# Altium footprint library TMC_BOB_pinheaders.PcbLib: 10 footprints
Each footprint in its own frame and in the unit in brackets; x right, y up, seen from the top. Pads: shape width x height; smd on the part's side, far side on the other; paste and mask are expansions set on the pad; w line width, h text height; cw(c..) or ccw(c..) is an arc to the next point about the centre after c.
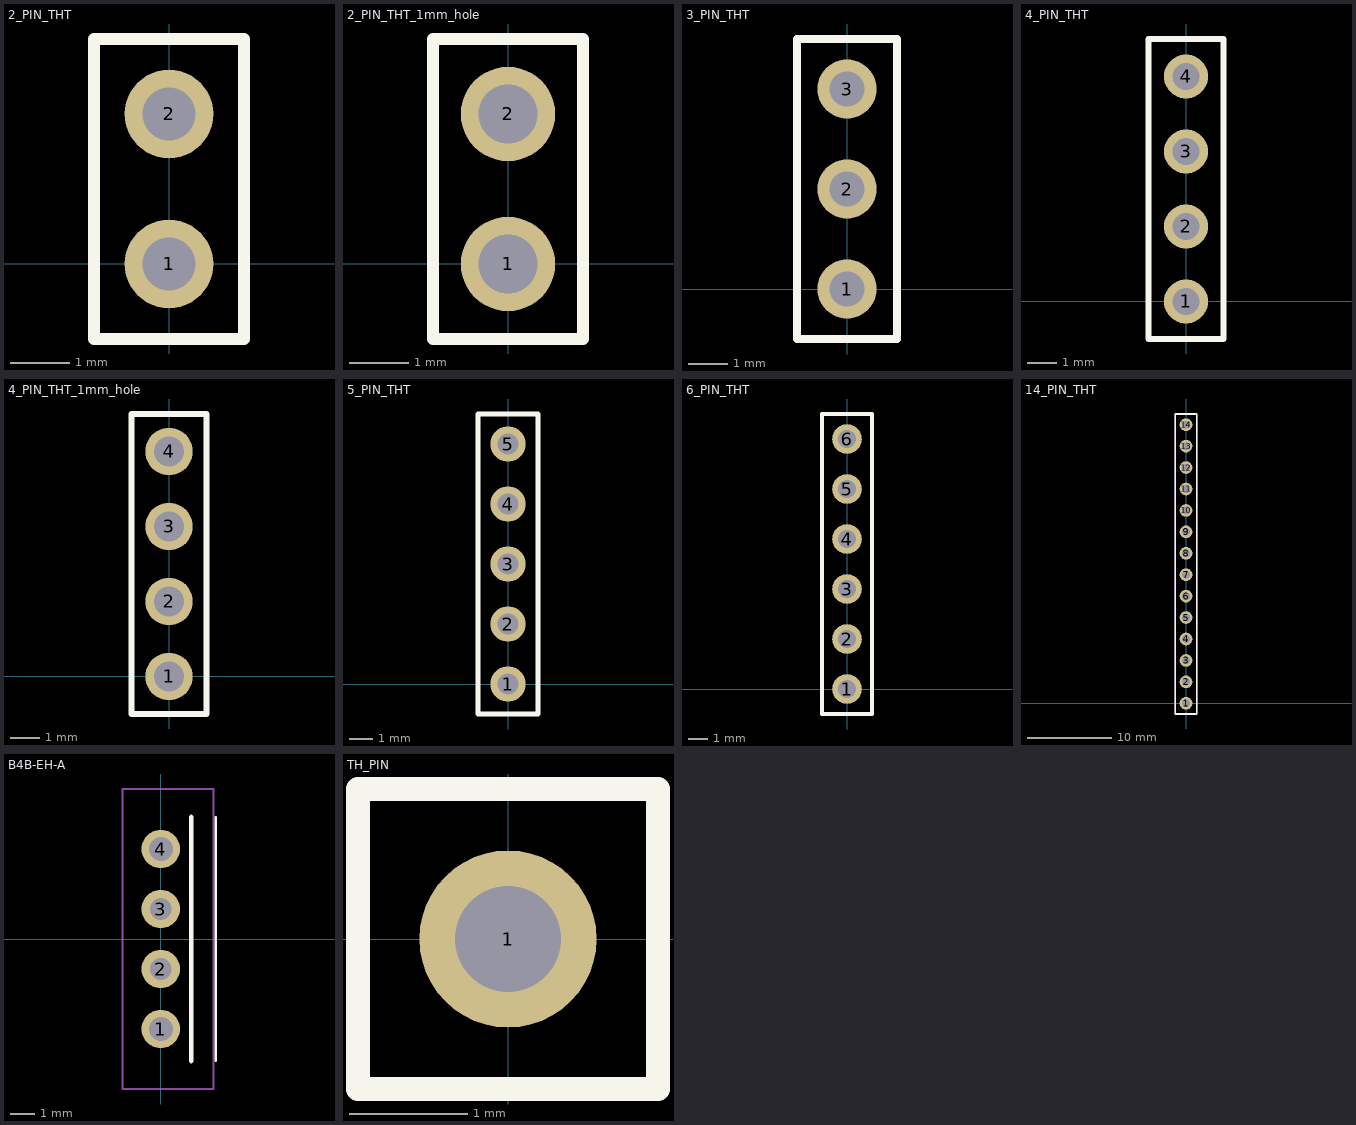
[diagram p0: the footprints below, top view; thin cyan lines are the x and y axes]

## 2_PIN_THT [mm]
pads (2):
  round 1.5 hole 0.9: 1(0,0) 2(0,2.54)
Top Overlay:
  lines w0.2: -1.27,-1.27 -1.27,3.81 1.27,3.81 1.27,-1.27 -1.27,-1.27
Bottom Overlay:
  lines w0.2: -1.27,-1.27 -1.27,3.81 1.27,3.81 1.27,-1.27 -1.27,-1.27
TopAsm:
  lines w0.051: -1.27,-1.27 -1.27,3.81 1.27,3.81 1.27,-1.27 -1.27,-1.27

## 2_PIN_THT_1mm_hole [mm]
pads (2):
  round 1.6 hole 1: 1(0,0) 2(0,2.54)
Top Overlay:
  lines w0.2: -1.27,-1.27 1.27,-1.27 1.27,3.81 -1.27,3.81 -1.27,-1.27
Bottom Overlay:
  lines w0.2: -1.27,-1.27 1.27,-1.27 1.27,3.81 -1.27,3.81 -1.27,-1.27
TopAsm:
  lines w0.051: -1.27,-1.27 1.27,-1.27 1.27,3.81 -1.27,3.81 -1.27,-1.27

## 3_PIN_THT [mm]
pads (3):
  round 1.5 hole 0.9: 1(0,0) 2(0,2.54) 3(0,5.08)
Top Overlay:
  lines w0.2: -1.27,-1.27 -1.27,6.35 1.27,6.35 1.27,-1.27 -1.27,-1.27
Bottom Overlay:
  lines w0.2: -1.27,-1.27 -1.27,6.35 1.27,6.35 1.27,-1.27 -1.27,-1.27
TopAsm:
  lines w0.051: -1.27,-1.27 1.27,-1.27 1.27,6.35 -1.27,6.35 -1.27,-1.27

## 4_PIN_THT [mm]
pads (4):
  round 1.5 hole 0.9: 1(0,0) 2(0,2.54) 3(0,5.08) 4(0,7.62)
Top Overlay:
  lines w0.2: -1.27,-1.27 -1.27,8.89 1.27,8.89 1.27,-1.27 -1.27,-1.27
Bottom Overlay:
  lines w0.2: -1.27,-1.27 1.27,-1.27 1.27,8.89 -1.27,8.89 -1.27,-1.27
TopAsm:
  lines w0.051: -1.27,-1.27 1.27,-1.27 1.27,8.89 -1.27,8.89 -1.27,-1.27

## 4_PIN_THT_1mm_hole [mm]
pads (4):
  round 1.6 hole 1: 1(0,0) 2(0,2.54) 3(0,5.08) 4(0,7.62)
Top Overlay:
  lines w0.2: -1.27,-1.27 -1.27,8.89 1.27,8.89 1.27,-1.27 -1.27,-1.27
Bottom Overlay:
  lines w0.2: -1.27,-1.27 1.27,-1.27 1.27,8.89 -1.27,8.89 -1.27,-1.27
TopAsm:
  lines w0.051: -1.27,-1.27 1.27,-1.27 1.27,8.89 -1.27,8.89 -1.27,-1.27

## 5_PIN_THT [mm]
pads (5):
  round 1.5 hole 0.9: 1(0,0) 2(0,2.54) 3(0,5.08) 4(0,7.62) 5(0,10.16)
Top Overlay:
  lines w0.2: -1.27,-1.27 1.27,-1.27 1.27,11.43 -1.27,11.43 -1.27,-1.27
Bottom Overlay:
  lines w0.2: -1.27,-1.27 1.27,-1.27 1.27,11.43 -1.27,11.43 -1.27,-1.27
TopAsm:
  lines w0.051: -1.27,-1.27 1.27,-1.27 1.27,11.43 -1.27,11.43 -1.27,-1.27

## 6_PIN_THT [mm]
pads (6):
  round 1.5 hole 0.9: 1(0,0) 2(0,2.54) 3(0,5.08) 4(0,7.62) 5(0,10.16) 6(0,12.7)
Top Overlay:
  lines w0.2: -1.27,-1.27 -1.27,13.97 1.27,13.97 1.27,-1.27 -1.27,-1.27
Bottom Overlay:
  lines w0.2: -1.27,-1.27 -1.27,13.97 1.27,13.97 1.27,-1.27 -1.27,-1.27
TopAsm:
  lines w0.051: -1.27,-1.27 1.27,-1.27 1.27,13.97 -1.27,13.97 -1.27,-1.27

## 14_PIN_THT [mm]
pads (14):
  round 1.5 hole 0.9: 1(0,0) 2(0,2.54) 3(0,5.08) 4(0,7.62) 5(0,10.16) 6(0,12.7) 7(0,15.24) 8(0,17.78) 9(0,20.32) 10(0,22.86) 11(0,25.4) 12(0,27.94) 13(0,30.48) 14(0,33.02)
Top Overlay:
  lines w0.2: -1.27,-1.27 1.27,-1.27 1.27,34.29 -1.27,34.29 -1.27,-1.27
Bottom Overlay:
  lines w0.2: -1.27,-1.27 -1.27,34.29 1.27,34.29 1.27,-1.27 -1.27,-1.27
TopAsm:
  lines w0.2: -1.27,-1.27 1.27,-1.27 1.27,13.97 1.27,29.21 1.27,34.29 -1.27,34.29 -1.27,29.21 -1.27,13.97 -1.27,-1.27

## B4B-EH-A [mm]
pads (4):
  round 1.6 hole 1: 1(0,-3.75) 4(0,3.75)
  round 1.6 hole 0.9: 2(0,-1.25) 3(0,1.25)
Top Overlay:
  lines w0.1: 2.286,-5.08 2.286,5.08
  lines w0.2: 1.27,-5.08 1.27,5.08
Bottom Overlay:
  lines w0.2: 1.27,-5.08 1.27,5.08
TopAsm:
  lines w0.051: 1.27,-5.08 1.27,5.08
  lines w0.075: -1.6,-6.25 2.2,-6.25 2.2,6.25 -1.6,6.25 -1.6,-6.25
3D body "B4B-EH-A.STEP": height 6, standoff -3.2, extent -1.6,-6.25 2.2,6.25

## TH_PIN [mm]
pads (1):
  round 1.5 hole 0.9: 1(0,0)
Top Overlay:
  lines w0.2: -1.27,-1.27 -1.27,1.27 1.27,1.27 1.27,-1.27 -1.27,-1.27
Bottom Overlay:
  lines w0.2: -1.27,-1.27 -1.27,1.27 1.27,1.27 1.27,-1.27 -1.27,-1.27
TopAsm:
  lines w0.1: -1.27,-1.27 -1.27,1.27 1.27,1.27 1.27,-1.27 -1.27,-1.27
